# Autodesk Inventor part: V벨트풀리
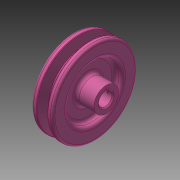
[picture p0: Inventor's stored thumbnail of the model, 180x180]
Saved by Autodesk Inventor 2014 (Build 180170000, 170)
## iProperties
Created: 2015-11
Part Number: V벨트풀리
Material: 강철, 탄소
Document SubType Name: Modeling
Designer: mduedu
Density: 1 g/cm^3
Appearance: 분홍색
Author: mduedu
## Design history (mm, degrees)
sketch "스케치1"
  geometry: L1 (-9.5, 0)-(9.5, 0); L2 (0, 0)-(0, 37.7); L3 (-4.825, 37.7)-(-9.5, 37.7); L4 (-9.5, 37.7)-(-9.5, 0); L5 (0, 28.7)-(-2.074, 28.7); L6 (-2.074, 28.7)-(-4.825, 37.7); L7 (4.825, 37.7)-(9.5, 37.7); L8 (9.5, 37.7)-(9.5, 0); L9 (0, 28.7)-(2.074, 28.7); L10 (2.074, 28.7)-(4.825, 37.7); L11 (-9.5, 35)-(9.5, 35); 3 further points
  constraints: 22 end point, 7 point on line, 4 perpendicular, 3 symmetric about line, 1 coincident, 1 horizontal, 1 horizontal alignment, 1 midpoint, 1 vertical
  dimensions: "d0" = 19 distance of L1.start L1.end; "d2" = 75.4 diameter of L2.end L1 (derived); "d3" = 34 deg angle of L10 L6; "d4" = 6.3 distance between parallel lines of L11 L9; "d5" = 2.7 distance between parallel lines of L7 L11; "d6" = 8 distance of point (4, 35) point (-4, 35); "d7" = 70 diameter of L11 L1
revolve "회전1" sketch "스케치1" stored, may be unused: angle "d8" = 90 deg
sketch "스케치2"
  geometry: C1 r 24 at (0, 0); C2 r 11 at (0, 0); 1 further point
  constraints: 2 centre point, 2 coincident
  dimensions: "d9" = 48 diameter of C1; "d10" = 22 diameter of C2
extrude "돌출1" cut sketch "스케치2" distance "d11" = 6; taper "d12" = 0 deg
extrude "돌출3" join sketch "스케치2" distance "d37" = 10; taper "d38" = 0 deg
fillet "모깎기1" dims "d13" = 3
fillet "모깎기2" dims "d14" = 3
fillet "모깎기3" dims "d15" = 1, "d16" = 0.5, "d17" = 2
hole "구멍1" diameter "d20" = 12; stored, may be unused: countersink angle "d24" = 90 deg, drill point angle "d26" = 118 deg; dims "d21" = 6, "d22" = 4, "d23" = 2, "d25" = 8, "d39" = 10, "d40" = 10
sketch "스케치3"
  geometry: L1 (-2, 0)-(2, 0); L2 (2, 0)-(2, 7.8); L3 (2, 7.8)-(-2, 7.8); L4 (-2, 7.8)-(-2, 0); 2 further points
  constraints: 8 end point, 2 parallel, 1 coincident, 1 horizontal, 1 midpoint, 1 perpendicular
  dimensions: "d27" = 4 distance of L2.end L3.end; "d29" = 7.8 distance of L3.end L1.start
extrude "돌출2" cut sketch "스케치3" stored distance "d30" = 6; taper "d31" = 0 deg
chamfer "모따기1" distance "d32" = 1; stored, may be unused: second distance "d33" = 2, angle "d34" = 45 deg
node "작업 평면1"
sketch "스케치4"
  geometry: L1 (-19, 11)-(-19, -11) reference; 2 further points
  constraints: 1 horizontal alignment
  dimensions: "d41" = 25 distance from line of point (6, 0) L1
hole "구멍2" sketch "스케치4" at (6, 0) diameter "d42" = 2.459; stored, may be unused: countersink angle "d46" = 90 deg, drill point angle "d48" = 118 deg; dims "d43" = 6, "d44" = 4, "d45" = 2, "d47" = 8
chamfer "모따기2" distance "d49" = 1; stored, may be unused: second distance "d50" = 2, angle "d51" = 45 deg
node "솔리드1"
mirror "대칭1"
